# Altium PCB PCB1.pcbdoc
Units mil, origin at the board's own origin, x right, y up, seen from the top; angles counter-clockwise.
Board outline 2445 x 1750 mil, 2 copper layers (Top Layer, Bottom Layer); 21 components, 25 nets, 99 pads, 39 vias.
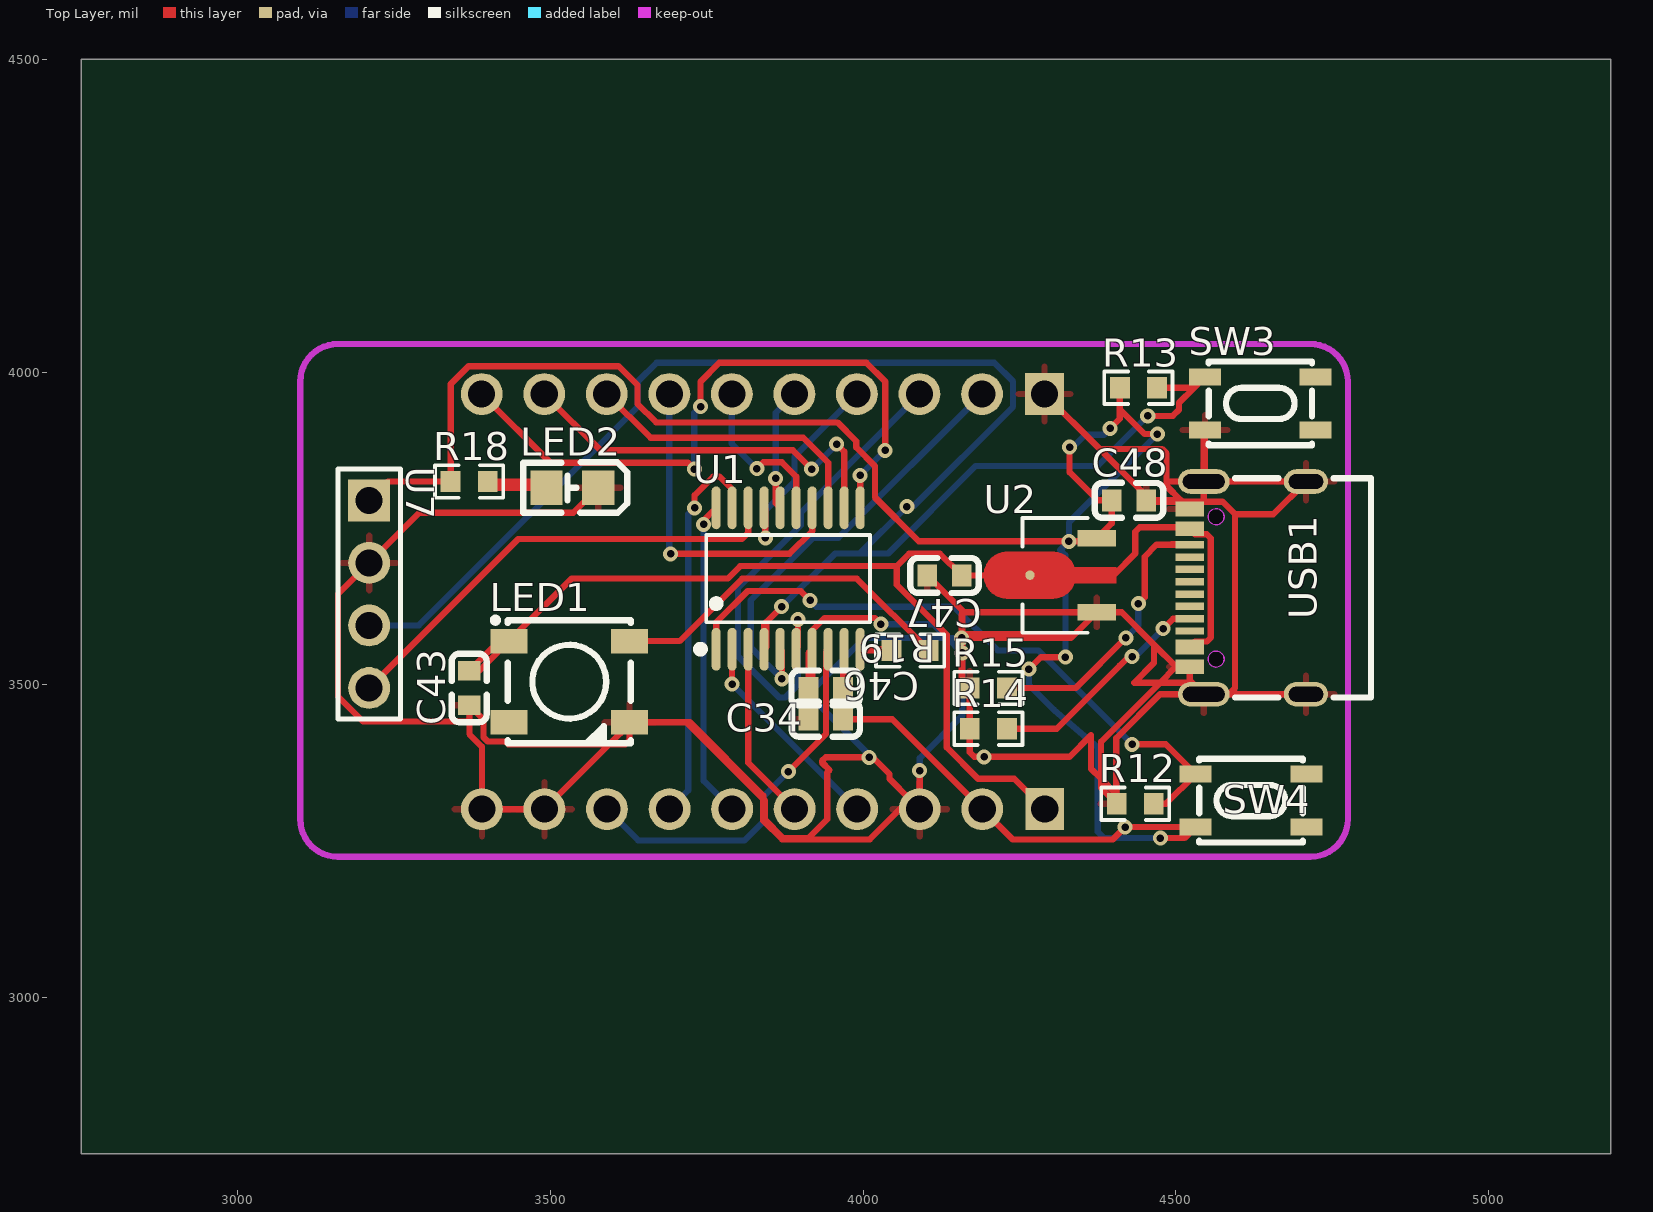
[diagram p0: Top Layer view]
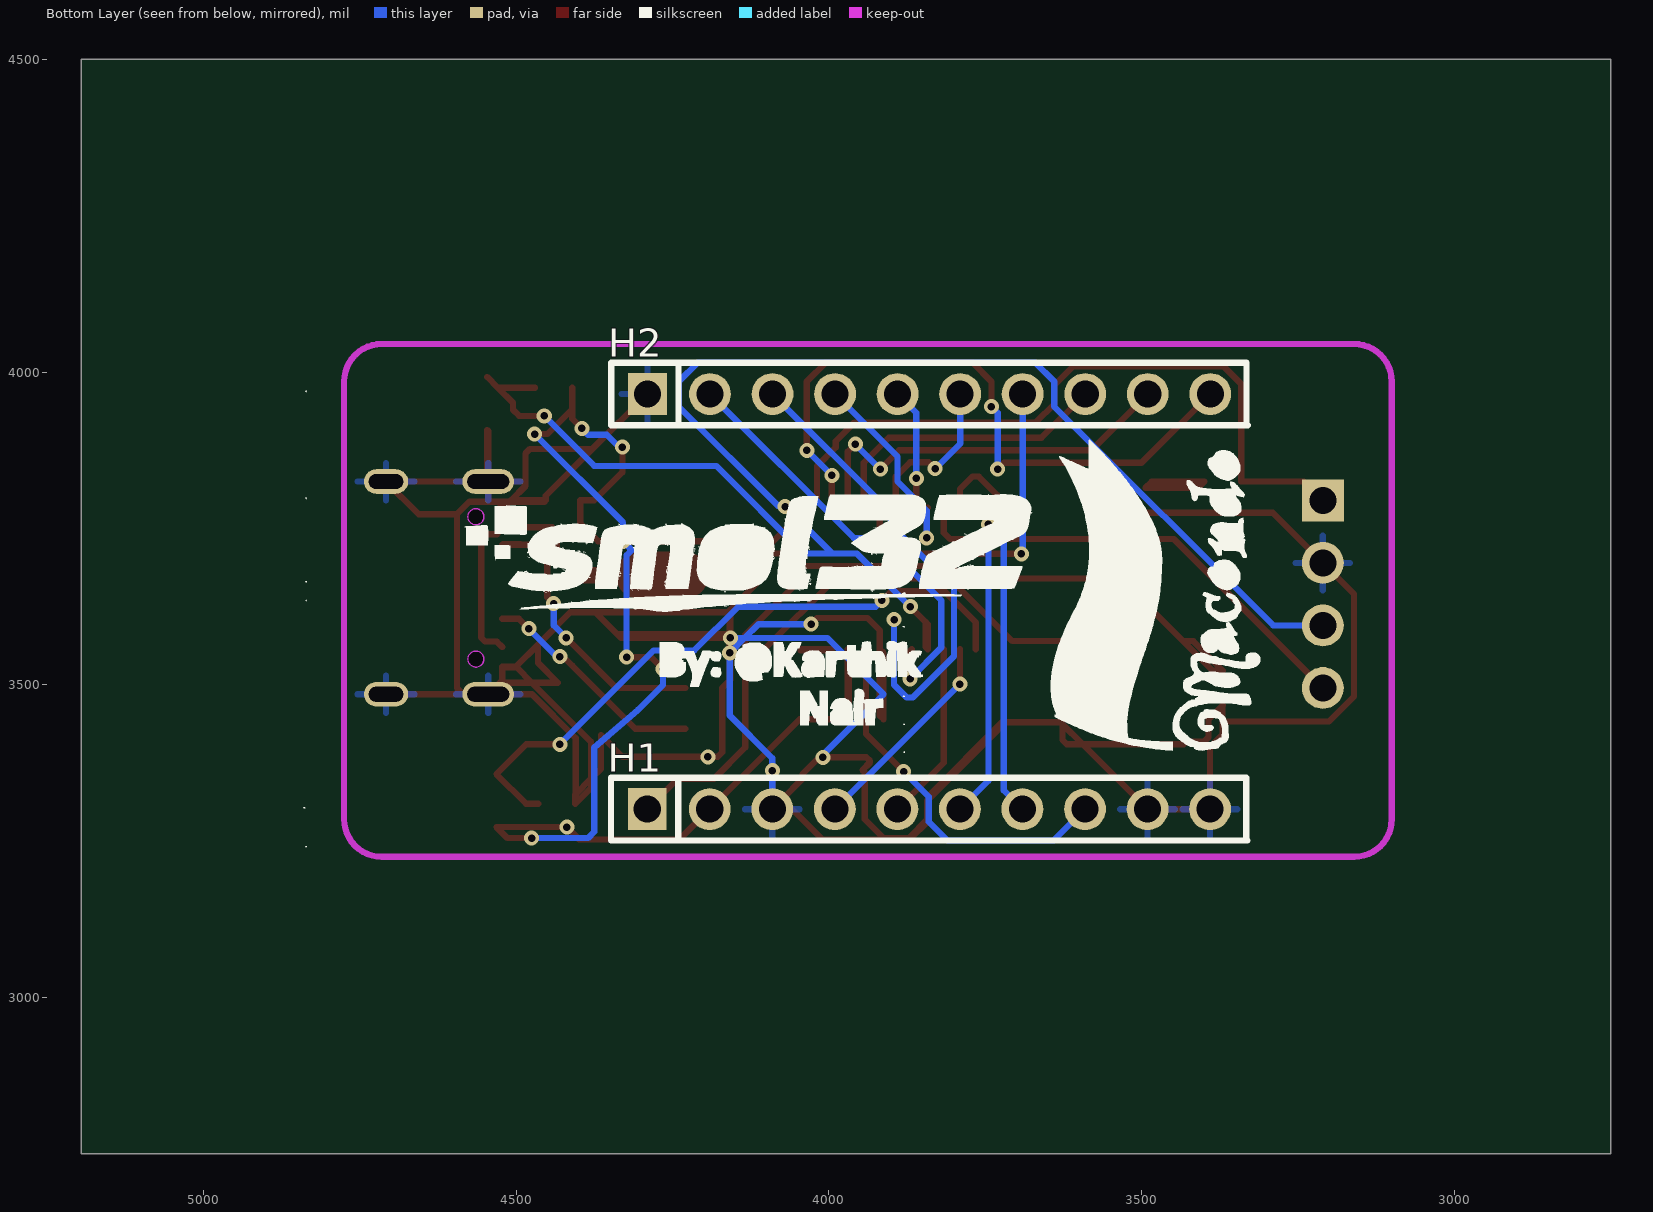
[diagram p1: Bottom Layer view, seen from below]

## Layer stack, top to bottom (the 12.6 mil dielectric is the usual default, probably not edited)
Top Layer: signal copper (thickness not stored)
Dielectric: dielectric 12.6, FR-4, Dk 4.8
Bottom Layer: signal copper (thickness not stored)

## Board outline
5195,2750 2750,2750 2750,4500 5195,4500

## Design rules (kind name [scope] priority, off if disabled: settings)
BoardOutlineClearance copperThickness1oz [All] p0: genericclearance=10 ignorepadtopadclearanceinfootprint=FALSE except(0: Arc-SplitContinuation Track-SplitContinuation SMDPad-SplitContinuation THPad-SplitContinuation Via-SplitContinuation Fill-SplitContinuation Poly-SplitContinuation Region-SplitContinuation Text-SplitContinuation; 6: Track-CutoutEdge SMDPad-CutoutEdge THPad-CutoutEdge Via-CutoutEdge Region-CutoutEdge; 11.8: Track-OutlineEdge SMDPad-OutlineEdge THPad-OutlineEdge Via-OutlineEdge Fill-OutlineEdge Region-OutlineEdge Poly-OutlineEdge Text-OutlineEdge Fill-CutoutEdge)
BoardOutlineClearance copperThickness2oz [All] p0: genericclearance=10 ignorepadtopadclearanceinfootprint=FALSE except(0: Arc-SplitContinuation Track-SplitContinuation SMDPad-SplitContinuation THPad-SplitContinuation Via-SplitContinuation Fill-SplitContinuation Poly-SplitContinuation Region-SplitContinuation Text-SplitContinuation; 6: Track-CutoutEdge SMDPad-CutoutEdge THPad-CutoutEdge Via-CutoutEdge Region-CutoutEdge; 11.8: Track-OutlineEdge SMDPad-OutlineEdge THPad-OutlineEdge Via-OutlineEdge Fill-OutlineEdge Region-OutlineEdge Poly-OutlineEdge Text-OutlineEdge Fill-CutoutEdge)
Clearance copperThickness1oz [(InNet('VCC') OR InNet('GND') OR InNet('5V') OR InNet('PD0') OR InNet('PD2') OR InNet('PD3') OR InNet('PD6') OR InNet('PD5') OR InNet('PC1') OR InNet('PC2') OR InNet('PC3') OR InNet('PC4') OR InNet('PC5') OR InNet('PC6') OR InNet('PC7') OR InNet('PA2') OR InNet('PA1') OR InNet('$1N1874') OR InNet('$1N1298') OR InNet('BOOT_PIN') OR InNet('NRST') OR InNet('$1N971') OR InNet('$1N974') OR InNet('RGBLD') OR InNet('SWDIO'))] p1: gap=7 ignorepadtopadclearanceinfootprint=FALSE except(4: Track-Track; 6: Track-SMDPad SMDPad-SMDPad Track-THPad SMDPad-THPad THPad-THPad Track-Via SMDPad-Via THPad-Via Via-Via SMDPad-Fill THPad-Fill Via-Fill Fill-Fill Track-Region SMDPad-Region THPad-Region Via-Region Region-Region Track-Poly SMDPad-Poly THPad-Poly Via-Poly Fill-Poly Region-Poly Poly-Poly Track-Text SMDPad-Text THPad-Text Via-Text Fill-Text Region-Text Poly-Text Text-Text; 6.9: Track-Hole SMDPad-Hole THPad-Hole Via-Hole Fill-Hole Region-Hole Poly-Hole Text-Hole Sheet-Hole; 11.8: Track-Fill Fill-Region Track-Sheet SMDPad-Sheet THPad-Sheet Via-Sheet Fill-Sheet Region-Sheet Poly-Sheet Text-Sheet)
Clearance copperThickness2oz [All] p1: gap=7 ignorepadtopadclearanceinfootprint=FALSE except(6: Track-SMDPad SMDPad-SMDPad Track-THPad SMDPad-THPad THPad-THPad Track-Via SMDPad-Via THPad-Via Via-Via SMDPad-Fill THPad-Fill Via-Fill Fill-Fill Track-Region SMDPad-Region THPad-Region Via-Region Region-Region Track-Poly SMDPad-Poly THPad-Poly Via-Poly Fill-Poly Region-Poly Poly-Poly Track-Text SMDPad-Text THPad-Text Via-Text Fill-Text Region-Text Poly-Text Text-Text; 6.9: Track-Hole SMDPad-Hole THPad-Hole Via-Hole Fill-Hole Region-Hole Poly-Hole Text-Hole Sheet-Hole; 8: Track-Track; 11.8: Track-Fill Fill-Region Track-Sheet SMDPad-Sheet THPad-Sheet Via-Sheet Fill-Sheet Region-Sheet Poly-Sheet Text-Sheet)
DiffPairsRouting differentialPair [All] p1: maxuncoupledlength=10 minlimit=6 maxlimit=6 mostfreqgap=6 toplayer_minwidth=5 toplayer_prefwidth=10 toplayer_maxwidth=100 bottomlayer_minwidth=5 bottomlayer_prefwidth=10 bottomlayer_maxwidth=100
PasteMaskExpansion pasteMaskExpansion [All] p1: expansion=0
PlaneConnect innerPlane [All] p1: planeconnectstyle=Relief reliefexpansion=20 reliefentries=4 reliefconductorwidth=10 reliefairgap=10
PolygonConnect copperRegion [All] p1: connectstyle=Relief reliefentries=4 reliefconductorwidth=10 polygonreliefangle="90 Angle" airgapwidth=10
RoutingVias viaSize [All] p1: viastyle="Through Hole" holewidth=12.0078 minholewidth=11.811 maxholewidth=248.0314 width=24.0158 minwidth=19.685 maxwidth=393.7008
SolderMaskExpansion solderMaskExpansion [All] p1: useseparateexpansions=TRUE expansion=2 expansionbottom=2
Width copperThickness1oz [All] p1: maxlimit=100 minlimit=5 preferedwidth=10
Width copperThickness2oz [All] p1: maxlimit=100 minlimit=8 preferedwidth=10

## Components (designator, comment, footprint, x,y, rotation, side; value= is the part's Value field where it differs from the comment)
C34 "FCC0603B104K500CT" C0603 3940,3445 r0 top
C43 "FCC0603B104K500CT" C0603 3370,3495 r90 top
C46 "CGA0603X5R105K500JT" C0603 3940,3495 r180 top
C47 "CL10A475KP8NNNC" C0603 4130,3675 r180 top
C48 "CL10A475KP8NNNC" C0603 4425,3795 r0 top
H1 "2.54-1*10" HDR-TH_10P-P2.54-V-M 3840.33,3301.26 r180 bottom
H2 "2.54-1*10" HDR-TH_10P-P2.54-V-M 3840,3965 r180 bottom
LED1 "WS2812B-B/T" LED-SMD_4P-L5.0-W5.0-TL_WS2812B-B 3530,3505 r0 top
LED2 "YLED0805G" LED0805-FD-GREEN 3535,3815 r0 top
R12 "FRC0603J103 TS" R0603 4435,3310 r0 top
R13 "FRC0603J103 TS" R0603 4440,3975 r0 top
R14 "FRC0603F5101TS" R0603 4200,3430 r0 top
R15 "FRC0603F5101TS" R0603 4200,3495 r0 top
R18 "FRC0603J331 TS" R0603 3370,3825 r0 top
R19 "FRC0603J331 TS" R0603 4075,3555 r180 top
SW3 "TS-1089S-02526" SW-SMD_4P-L4.2-W3.3-P2.15-LS5.1 4635,3950 r0 top
SW4 "TS-1089S-02526" SW-SMD_4P-L4.2-W3.3-P2.15-LS5.1 4620,3315 r0 top
U1 "CH32V006F8P6_C52753342" TSSOP-20_L6.5-W4.4-P0.65-LS6.4-BL 3880,3670 r0 top
U2 "XC6206-3.3V_C7603199" SOT-89-3_L4.3-W2.3-P1.50-LS4.3-BR 4320,3675 r0 top
U7 "2.54-1*4" HDR-TH_4P-P2.54-V-M-1 3210,3645 r270 top
USB1 "TYPE-C16PIN" USB-C-SMD_TYPE-C16PIN 4615,3655 r90 top

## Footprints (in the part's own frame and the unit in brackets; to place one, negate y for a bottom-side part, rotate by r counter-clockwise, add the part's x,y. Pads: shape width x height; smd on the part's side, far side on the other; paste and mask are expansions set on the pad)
C0603 [mm]
  rect 0.8x0.9 smd: 1(-0.7,0) 2(0.7,0)
  silkscreen extent -1.39,-0.71 1.39,0.71
HDR-TH_4P-P2.54-V-M-1 [mm]
  rect 1.7x1.7 hole 1.1: 1(-3.81,0)
  round 1.7 hole 1.1: 2(-1.27,0) 3(1.27,0) 4(3.81,0)
  silkscreen extent -5.08,-1.27 5.08,1.27
HDR-TH_10P-P2.54-V-M [mm]
  rect 1.575x1.7 hole 1.1: 1(-11.43,0)
  round 1.7 hole 1.1: 2(-8.89,0) 3(-6.35,0) 4(-3.81,0) 5(-1.27,0) 6(1.27,0) 7(3.81,0) 8(6.35,0) 9(8.89,0) 10(11.43,0)
  silkscreen extent -12.9,-1.27 12.95,1.27
LED0805-FD-GREEN [mil]
  rect 51.2x55.1 smd: 1(-41.35,0) 2(41.35,0)
  silkscreen extent -78,-40 88,41
LED-SMD_4P-L5.0-W5.0-TL_WS2812B-B [mm]
  rect 1.5x1 smd: 1(-2.45,1.65) 2(-2.45,-1.65) 3(2.45,-1.65) 4(2.45,1.65)
  silkscreen extent -3.1,-2.5 2.5,2.6
R0603 [mil]
  rect 31.75x34.02 smd: 1(-29.66,0) 2(29.66,0)
  silkscreen extent -55,-26 55,26
SOT-89-3_L4.3-W2.3-P1.50-LS4.3-BR [mm]
  rect 1.575x0.672 smd: 1(1.356,-1.5) 3(1.356,1.5)
  round 0.38 smd: 2(-1.356,0.009)
  Top Layer region: -2.283,0.959 -0.429,0.959 -0.384,0.958 -0.34,0.955 -0.296,0.949 -0.252,0.942 -0.208,0.933 -0.165,0.921 -0.123,0.908 -0.081,0.893 -0.04,0.875 0,0.856 0.04,0.835 0.078,0.812 0.115,0.788 0.151,0.761 0.185,0.733 0.219,0.704 0.251,0.673 0.281,0.64 0.31,0.606 0.337,0.571 0.362,0.534 0.386,0.497 0.408,0.458 0.428,0.418 0.447,0.339 2.144,0.339 2.144,-0.321 0.447,-0.321 0.428,-0.401 0.408,-0.44 0.386,-0.479 0.362,-0.517 0.337,-0.553 0.31,-0.588 0.281,-0.622 0.251,-0.655 0.219,-0.686 0.185,-0.716 0.151,-0.744 0.115,-0.77 0.078,-0.795 0.04,-0.818 0,-0.839 -0.04,-0.858 -0.081,-0.875 -0.123,-0.89 -0.165,-0.904 -0.208,-0.915 -0.252,-0.925 -0.296,-0.932 -0.34,-0.937 -0.384,-0.94 -0.429,-0.941 -2.283,-0.941 -2.328,-0.94 -2.372,-0.937 -2.416,-0.932 -2.46,-0.925 -2.504,-0.915 -2.547,-0.904 -2.589,-0.89 -2.631,-0.875 -2.672,-0.858 -2.713,-0.839 -2.752,-0.818 -2.79,-0.795 -2.827,-0.77 -2.863,-0.744 -2.898,-0.716 -2.931,-0.686 -2.963,-0.655 -2.993,-0.622 -3.022,-0.588 -3.049,-0.553 -3.075,-0.517 -3.098,-0.479 -3.12,-0.44 -3.141,-0.401 -3.159,-0.36 -3.175,-0.318 -3.189,-0.276 -3.202,-0.233 -3.212,-0.19 -3.22,-0.146 -3.227,-0.102 -3.231,-0.058 -3.233,-0.013 -3.233,0.031 -3.231,0.076 -3.227,0.12 -3.22,0.164 -3.212,0.208 -3.202,0.251 -3.189,0.294 -3.175,0.336 -3.159,0.377 -3.141,0.418 -3.12,0.458 -3.098,0.497 -3.075,0.534 -3.049,0.571 -3.022,0.606 -2.993,0.64 -2.963,0.673 -2.931,0.704 -2.898,0.733 -2.863,0.761 -2.827,0.788 -2.79,0.812 -2.752,0.835 -2.713,0.856 -2.672,0.875 -2.631,0.893 -2.589,0.908 -2.547,0.921 -2.504,0.933 -2.46,0.942 -2.416,0.949 -2.372,0.955 -2.328,0.958
  silkscreen extent -1.66,-2.33 0.99,2.33
SW-SMD_4P-L4.2-W3.3-P2.15-LS5.1 [mm]
  rect 1.3x0.7 smd: 1(-2.25,1.075) 2(2.25,1.075) 3(-2.25,-1.075) 4(2.25,-1.075)
  silkscreen extent -2.1,-1.7 2.1,1.7
TSSOP-20_L6.5-W4.4-P0.65-LS6.4-BL [mil]
  oval 14.33x68.58 smd: 1(-115.16,-113.03) 2(-89.57,-113.03) 3(-63.98,-113.03) 4(-38.39,-113.03) 5(-12.79,-113.03) 6(12.8,-113.03) 7(38.39,-113.03) 8(63.98,-113.03) 9(89.57,-113.03) 10(115.16,-113.03) 11(115.16,113.03) 12(89.57,113.03) 13(63.98,113.03) 14(38.39,113.03) 15(12.8,113.03) 16(-12.79,113.03) 17(-38.39,113.03) 18(-63.98,113.03) 19(-89.57,113.03) 20(-115.16,113.03)
  silkscreen extent -146,-119 131,70
USB-C-SMD_TYPE-C16PIN [mm]
  oval 1x2.1 hole 0.6 slot 1.7 at 90 deg: 1(-4.32,1.787) 2(4.32,1.787)
  oval 1x1.8 hole 0.6 slot 1.4 at 90 deg: 3(-4.32,-2.362) 4(4.32,-2.362)
  rect 0.6x1.15 smd: A1B12(-3.2,2.362) A4B9(-2.4,2.362) B1A12(3.2,2.362) B4A9(2.4,2.362)
  rect 0.3x1.15 smd: A5(-1.25,2.362) A6(-0.25,2.362) A7(0.25,2.362) A8(1.25,2.362) B5(1.75,2.362) B6(0.75,2.362) B7(-0.75,2.362) B8(-1.75,2.362)
  Board Outline Layer circle w0.005: c2.89,1.288 r0.325
  Board Outline Layer circle w0.005: c-2.89,1.288 r0.325
  Board Outline Layer region: 2.89,0.963 2.749,0.995 2.636,1.085 2.573,1.216 2.573,1.36 2.636,1.491 2.749,1.581 2.89,1.613 2.89,1.613 3.031,1.581 3.144,1.491 3.207,1.36 3.207,1.216 3.144,1.085 3.031,0.995 2.89,0.963
  Board Outline Layer region: -2.89,0.963 -3.031,0.995 -3.144,1.085 -3.207,1.216 -3.207,1.36 -3.144,1.491 -3.031,1.581 -2.89,1.613 -2.89,1.613 -2.749,1.581 -2.636,1.491 -2.573,1.36 -2.573,1.216 -2.636,1.085 -2.749,0.995 -2.89,0.963
  Multi-Layer board cut-out: 2.89,0.963 2.749,0.995 2.636,1.085 2.573,1.216 2.573,1.36 2.636,1.491 2.749,1.581 2.89,1.613 2.89,1.613 3.031,1.581 3.144,1.491 3.207,1.36 3.207,1.216 3.144,1.085 3.031,0.995 2.89,0.963
  Multi-Layer board cut-out: -2.89,0.963 -3.031,0.995 -3.144,1.085 -3.207,1.216 -3.207,1.36 -3.144,1.491 -3.031,1.581 -2.89,1.613 -2.89,1.613 -2.749,1.581 -2.636,1.491 -2.573,1.36 -2.573,1.216 -2.636,1.085 -2.749,0.995 -2.89,0.963
  silkscreen extent -4.45,-5 4.45,0.52

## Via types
v1: diameter 24.02, hole 12.01, Top Layer to Bottom Layer, 39 vias

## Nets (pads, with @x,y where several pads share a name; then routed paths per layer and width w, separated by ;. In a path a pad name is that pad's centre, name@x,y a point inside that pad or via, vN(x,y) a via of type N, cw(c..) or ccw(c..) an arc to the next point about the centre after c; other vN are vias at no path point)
5V: C43.2 C47.1 H1.1 LED1.1 U2.2 USB1.A4B9 USB1.B4A9 | length 2140.1
  Top Layer w10: H1.1 4241.64,3349.96 4183.55,3349.96 4133.55,3399.96 4133.55,3579.96 4053.55,3659.96 4053.55,3689.96 ; USB1.A4B9 4530.69,3569.21 4549.18,3569.21 4555.61,3575.64 4555.61,3734.36 4549.18,3740.79 4530.69,3740.79 USB1.B4A9 4519.41,3752.07 4442.07,3752.07 4435,3745 4435,3710 4400.34,3675.34 U2.2 4266.26,3675 C47.1 4122.6,3709.96 4073.55,3709.96 4053.55,3689.96 ; LED1.1 3417.4,3569.96 C43.2 3386.14,3522.56 LED1.1 ; LED1.1 3533.55,3669.96 3783.55,3669.96 3803.55,3689.96 4053.55,3689.96
$1N971: R14.2 USB1.A5 | length 375.1
  Top Layer w10: R14.2 4309.66,3430 4410,3530.34 4424.66,3545 v1@4434.66,3545 ; v1(4479.66,3590) 4495.45,3605.79 USB1.A5
  Bottom Layer w10: v1@4424.66,3545 4434.66,3545 v1(4479.66,3590)
  other v1: 4430,3545
$1N974: R15.2 USB1.B5 | length 476.6
  Top Layer w10: R15.2 4340,3495 v1(4420,3575) ; v1(4440,3630) 4450,3640 4450,3705 4468.9,3723.9 4491.99,3723.9 ; 4491.99,3723.9 USB1.B5 4520.89,3725 4493.09,3725 4491.99,3723.9
  Bottom Layer w10: v1(4420,3575) 4440,3595 v1(4440,3630)
$1N1298: LED2.1 R18.2 | length 196.3
  Top Layer w10: R18.2 3483.65,3825 LED2.1 3409.66,3815 R18.2
$1N1874: LED1.4 R19.1 | length 567.2
  Top Layer w10: LED1.4 3706.45,3569.96 3806.45,3669.96 3989.7,3669.96 R19.1
BOOT_PIN: R12.2 SW4.1 U1.1 | length 1037.8
  Top Layer w10: U1.1 3764.84,3599.84 3815,3650 3900,3650 v1(3915,3635) ; v1(4430,3405) 4483.74,3405 SW4.1 4484.09,3310 R12.2
  Bottom Layer w10: v1(3915,3635) 3925,3625 4145,3625 4215,3555 4280,3555 v1(4430,3405)
GND: C34.1 C43.1 C46.2 C47.2 C48.2 H1.3 H1.9 H1.10 H2.1 LED1.3 LED2.2 R12.1 R14.1 R15.1 SW3.3 U1.7 U2.1 U7.2 USB1.1 USB1.2 USB1.3 USB1.4 USB1.A1B12 USB1.B1A12 | length 8217.2
  Top Layer w10: C43.1 C43.1@3370.33,3467.11 ; LED2.2 3536.35,3775 3290,3775 U7.2 3160.33,3645.33 3160.33,3481.26 3200.33,3441.26 3370.33,3441.26 ; v1(4028.39,3596.97) 4018.39,3606.97 3938.39,3606.97 3918.39,3586.97 U1.7 ; H1.3 H1.3@4074.52,3317.08 ; v1(4090.33,3362.89) 4090.33,3332.89 H1.3@4074.52,3317.08 ; C47.2 4158.39,3619.05 ; H2.1 4377.93,3877.07 ; USB1.3 USB1.1@4584.63,3484.92 ; 3370.33,3441.26 3370.33,3421.26 3390.33,3401.26 H1.10 H1.9 3594.07,3405 ; 3370.33,3441.26 C43.1@3370.33,3467.11 ; C43.1@3370.33,3467.11 3393.03,3444.41 3393.03,3415.81 3399.47,3409.37 3428.07,3409.37 3432.44,3405 3594.07,3405 ; 3594.07,3405 3619.38,3405 3626.45,3412.07 LED1.3@3626.45,3437.38 ; 3594.07,3405 LED1.3@3626.45,3437.38 ; LED1.3@3626.45,3437.38 LED1.3 3717.4,3440.04 ; 3717.4,3440.04 3840.33,3317.11 ; 3717.4,3440.04 3723.19,3440.04 3840.33,3322.89 3840.33,3317.11 ; 3840.33,3317.11 3842.44,3315 3842.44,3285 3872.44,3255 3912.44,3255 3942.44,3285 3942.44,3360 3946.22,3363.78 3934.14,3375.86 3934.14,3378.28 3940,3384.14 v1(4009.5,3384.14) 4015.36,3384.14 4042.18,3357.33 4042.18,3349.42 H1.3@4074.52,3317.08 ; 3840.33,3317.11 3840.33,3282.89 3870.33,3252.89 4010.33,3252.89 H1.3@4074.52,3317.08 ; U1.7 3912.44,3551.02 C46.2 C34.1 3918.39,3450.95 U1.7 ; v1(4157.44,3575) 4157.44,3507.9 R15.1@4158.39,3506.95 ; v1(4157.44,3575) 4157.44,3611.9 4158.39,3612.85 ; v1(4157.44,3575) v1@4158.39,3575 ; R15.1@4158.39,3506.95 v1(4158.39,3550.95) v1@4158.39,3575 ; R15.1@4158.39,3506.95 R15.1 R14.1 4170.34,3392.07 4177.41,3385 v1(4193.51,3385) 4330,3385 4364.22,3419.22 4364.22,3365.78 4380.34,3349.66 ; v1@4158.39,3575 v1@4158.39,3580.95 ; v1@4158.39,3575 4332.44,3575 4338.39,3580.95 ; v1@4158.39,3580.95 4338.39,3580.95 ; v1@4158.39,3580.95 4158.39,3612.85 ; 4158.39,3612.85 4158.39,3619.05 ; 4158.39,3612.85 4161.49,3615.95 ; 4158.39,3619.05 4161.49,3615.95 ; 4161.49,3615.95 U2.1 ; 4338.39,3580.95 U2.1 ; U2.1 4413.39,3615.95 4465,3564.35 ; 4377.93,3877.07 4477.93,3877.07 4485,3870 4485,3825.08 ; 4377.93,3877.07 4452.56,3802.44 C48.2 ; 4380.34,3349.66 4380.34,3409.01 4474.72,3503.39 ; 4380.34,3349.66 4380.34,3335 R12.1@4404.63,3310.71 ; 4380.34,3349.66 R12.1@4404.63,3325.37 ; R12.1@4404.63,3310.71 R12.1 4405.34,3324.66 R12.1@4404.63,3325.37 ; R12.1@4404.63,3310.71 R12.1@4404.63,3325.37 ; R12.1@4404.63,3325.37 4404.63,3414.92 4474.63,3484.92 USB1.1 ; C48.2 4507.97,3795 ; C48.2 4454.63,3792.93 4510.04,3792.93 ; 4465,3564.35 4465,3535 4433.39,3503.39 4474.72,3503.39 ; 4465,3564.35 USB1.A1B12@4500.34,3529.01 ; 4474.72,3503.39 USB1.1@4526.16,3503.39 ; 4474.72,3503.39 4499.25,3527.93 ; 4485,3825.08 4485,3817.97 4507.97,3795 ; 4485,3825.08 USB1.2 ; 4499.25,3527.93 USB1.A1B12@4500.34,3529.01 ; 4499.25,3527.93 4520.91,3527.93 USB1.A1B12 ; USB1.A1B12@4500.34,3529.01 USB1.A1B12 ; 4507.97,3795 4510.04,3792.93 ; 4510.04,3792.93 USB1.B1A12 4524.63,3783.62 4524.63,3792.93 ; 4510.04,3792.93 4524.63,3792.93 ; USB1.A1B12 4521.99,3507.56 USB1.1@4526.16,3503.39 ; 4524.63,3792.93 4544.63,3792.93 ; USB1.1@4526.16,3503.39 USB1.1 ; USB1.1 USB1.1@4584.63,3484.92 ; 4544.63,3792.93 USB1.2 ; 4544.63,3792.93 4574.63,3792.93 4594.63,3772.93 ; USB1.2 4546.42,3826.87 SW3.3 4544.63,3905.89 USB1.2 ; USB1.2 USB1.4 4655.86,3772.93 4594.63,3772.93 ; USB1.1@4584.63,3484.92 4594.63,3494.92 4594.63,3772.93
  Bottom Layer w10: v1@4014.5,3385 4012.44,3385 3912.44,3485 4002.44,3575 4134.34,3575 ; v1(4028.39,3596.97) 4112.37,3596.97 4134.34,3575 ; H1.3 v1(4090.33,3362.89) 4090.33,3382.89 4158.39,3450.95 v1(4158.39,3550.95) 4134.34,3575 ; v1(4157.44,3575) 4134.34,3575
NRST: R13.2 SW3.1 U1.4 U7.3 | length 2641
  Top Layer w10: v1(3869.66,3625) 3845,3600.34 ; v1(4455,3930) 4495,3930 4505,3940 4505,3950.91 4529.09,3975 ; R13.2 4529.09,3975 ; SW3.1 4529.09,3975 ; 3845,3600.34 3845,3560.36 U1.4 3841.61,3596.95 3845,3600.34
  Bottom Layer w10: U7.3 3289.66,3595 3639.66,3945 3639.66,3985 3669.66,4015 4209.66,4015 4239.66,3985 4239.66,3945 4079.66,3785 v1(4069.66,3785) 3994.66,3710 ; v1(3869.66,3625) 3909.66,3665 3910,3665 3955,3710 3994.66,3710 ; v1(4455,3930) 4375,3850 4180,3850 4040,3710 3994.66,3710
PA1: H2.2 U1.5 | length 701
  Top Layer w10: U1.5 3870,3554.18 v1(3870,3509.76)
  Bottom Layer w10: v1(3870,3509.76) 3820,3559.76 3820,3635 3920,3735 3960,3735 H2.2
PA2: H2.3 U1.6 | length 823.6
  Top Layer w10: U1.6 3895.6,3559.77 v1(3895.6,3604.17)
  Bottom Layer w10: v1(3895.6,3604.17) 3895.6,3499.77 3875.6,3479.77 3865.6,3479.77 3800,3545.37 3800,3655 3900,3755 3900,3775 H2.3
PC1: H2.10 U1.11 | length 1072.4
  Top Layer w10: H2.10 3500,3855 3720,3855 v1(3730,3845) ; v1(3740,3945) 3740,3985 3770,4015 4005.16,4015 4035.16,3985 v1(4035.16,3875) ; U1.11 v1(3995.16,3835)
  Bottom Layer w10: v1(3730,3845) 3730,3935 v1(3740,3945) ; v1(3995.16,3835) v1(4035.16,3875)
PC2: H2.9 U1.12 | length 640.8
  Top Layer w10: H2.9 3580,3875 3887.6,3875 v1(3917.6,3845) ; v1(3957.6,3885) 3969.57,3873.03 U1.12
  Bottom Layer w10: v1(3917.6,3845) v1(3957.6,3885)
PC3: H2.8 U1.13 | length 471.7
  Top Layer w10: H2.8 3660,3895 3904.23,3895 3943.98,3855.25 U1.13
PC4: H2.7 U1.14 | length 535
  Top Layer w10: v1(3691.97,3709.45) 3881.97,3709.45 3918.39,3745.87 U1.14
  Bottom Layer w10: H2.7 3690,3711.42 v1(3691.97,3709.45)
PC5: H2.6 U1.15 | length 262.1
  Top Layer w10: v1(3830,3845.83) 3840,3855.83 3870,3855.83 3892.8,3833.03 U1.15
  Bottom Layer w10: H2.6 3790,3885.83 v1(3830,3845.83)
PC6: H2.5 U1.16 | length 197.4
  Top Layer w10: v1(3860,3830.24) 3860,3790.24 U1.16
  Bottom Layer w10: v1(3860,3830.24) 3860,3935 H2.5
PC7: H2.4 U1.17 | length 339.5
  Top Layer w10: U1.17 3843.58,3781.06 v1(3843.58,3735)
  Bottom Layer w10: v1(3843.58,3735) 3843.58,3778.58 3890,3825 3890,3865 H2.4
PD0: H1.8 U1.8 | length 601.8
  Top Layer w10: v1(3880.33,3361.26) 3940.33,3421.26 3940.33,3553.32 U1.8
  Bottom Layer w10: H1.8 3640.33,3251.26 3810.33,3251.26 3840.33,3281.26 3840.33,3321.26 v1(3880.33,3361.26)
PD2: H1.7 U1.19 | length 629
  Top Layer w10: v1(3730.33,3783.03) 3730.33,3803.03 3760.33,3833.03 3770.33,3833.03 3790.33,3813.03 U1.19
  Bottom Layer w10: H1.7 3720.33,3331.26 3720.33,3773.03 v1(3730.33,3783.03)
PD3: H1.6 U1.20 | length 508.9
  Top Layer w10: v1(3744.84,3756.76) 3744.84,3763.03 U1.20
  Bottom Layer w10: v1(3744.84,3756.76) 3744.84,3346.76 H1.6
PD5: H1.4 U1.2 | length 338.5
  Top Layer w10: v1(3790.33,3501.26) U1.2@3790.33,3556.87
  Bottom Layer w10: v1(3790.33,3501.26) H1.4
PD6: H1.5 U1.3 | length 286.5
  Top Layer w10: U1.3 3816.02,3375.58 H1.5
RGBLD: R19.2 U1.10 | length 102
  Top Layer w10: U1.10 4043.37,3556.97 R19.2 3997.13,3555 U1.10
SWDIO: U1.18 U7.4 | length 748.8
  Top Layer w10: U7.4 3448.03,3733.03 3806.02,3733.03 3816.02,3743.03 U1.18
VCC: C34.2 C46.1 C48.1 H1.2 R13.1 R18.1 SW4.3 U1.9 U2.3 U7.1 | length 3781.5
  Top Layer w10: U7.1 3240,3825 R18.1 3340.34,3981.01 3368.92,4009.59 3608.92,4009.59 3638.92,3979.59 3638.92,3949.59 3668.92,3919.59 3958.92,3919.59 3988.92,3889.59 3988.92,3879.59 4018.92,3849.59 4018.92,3799.59 4088.92,3729.59 v1(4328.92,3729.59) 4368.92,3729.59 U2.3 4397.44,3758.11 C48.1 4375,3795 4330,3840 v1(4330,3880) ; v1(4265,3525) 4284.16,3544.16 v1(4323.35,3544.16) ; v1(4395,3910) 4410.34,3925.34 4410.34,3941.01 ; R13.1 4410.34,3941.01 ; v1(4470.34,3901.01) 4450.34,3901.01 4410.34,3941.01 ; v1(4475,3255) 4513.74,3255 SW4.3 v1(4418.92,3272.68) 4398.92,3252.68 4238.92,3252.68 H1.2 4046.6,3445 C34.2 ; C34.2 3969.57,3447.01 U1.9 3967.56,3554.96 C46.1 C34.2
  Bottom Layer w10: v1(4265,3525) 4265,3500 4305,3460 4375,3400 4375,3265 4385,3255 v1(4475,3255) ; v1(4323.35,3544.16) 4323.35,3707.31 4315,3715.67 v1(4328.92,3729.59) 4328.92,3759.59 v1(4470.34,3901.01) ; v1(4330,3880) 4335,3880 4355,3900 4385,3900 v1(4395,3910)
pads on no net: LED1.2 SW3.2 SW3.4 SW4.2 SW4.4 USB1.A6 USB1.A7 USB1.A8 USB1.B6 USB1.B7 USB1.B8

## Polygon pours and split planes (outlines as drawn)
GND on Bottom Layer (solid, remove dead copper, pour order 2): 3000,4250 4945,4250 4945,3000 3000,3000
GND on Top Layer (solid, remove dead copper, pour order 0): 3045,4145 4870,4145 4870,3125 3045,3125

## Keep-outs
Board Outline Layer:
  lines w10: 3100,3285 ccw(c3160,3285) 3160,3225 4715,3225 ccw(c4715,3285) 4775,3285 4775,3985 ccw(c4715,3985) 4715,4045 3160,4045 ccw(c3160,3985) 3100,3985 3100,3285

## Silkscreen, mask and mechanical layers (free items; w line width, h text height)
Bottom Silkscreen Layer:
  drawing of 74 lines, arcs and shapes, not listed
